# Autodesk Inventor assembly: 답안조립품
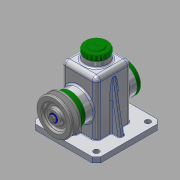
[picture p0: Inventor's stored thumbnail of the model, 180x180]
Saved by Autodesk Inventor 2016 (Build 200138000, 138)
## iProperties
Created: 2018-10
Part Number: 답안조립품
Document SubType Name: Weldment
Designer: user
Weld Material: Welded Aluminum-6061
Author: user
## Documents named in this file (14)
- C:\Users\user\Desktop\481016V1008\답안조립품.iam
- C:\Users\user\Desktop\481016V1008\본체.ipt
- C:\Users\user\Desktop\481016V1008\축.ipt
- C:\Users\user\Desktop\481016V1008\베어링 15 x 35 x 11.ipt
- C:\Users\user\Desktop\481016V1008\멈춤링 15 x 1.ipt
- C:\Users\user\Desktop\481016V1008\뒤커버.ipt
- C:\Users\user\Desktop\481016V1008\볼트 M4 x 10.ipt
- C:\Users\user\Desktop\481016V1008\앞커버.ipt
- C:\Users\user\Desktop\481016V1008\오일실 15 25 7.ipt
- C:\Users\user\Desktop\481016V1008\키 5 x 5 x 14.ipt
- C:\Users\user\Desktop\481016V1008\V-벨트풀리.ipt
- C:\Users\user\Desktop\481016V1008\와셔.ipt
- C:\Users\user\Desktop\481016V1008\볼트 M6 x 12.ipt
- C:\Users\user\Desktop\481016V1008\상부캡.ipt
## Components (1 placed, 1 different names)
1. V-벨트풀리:1
